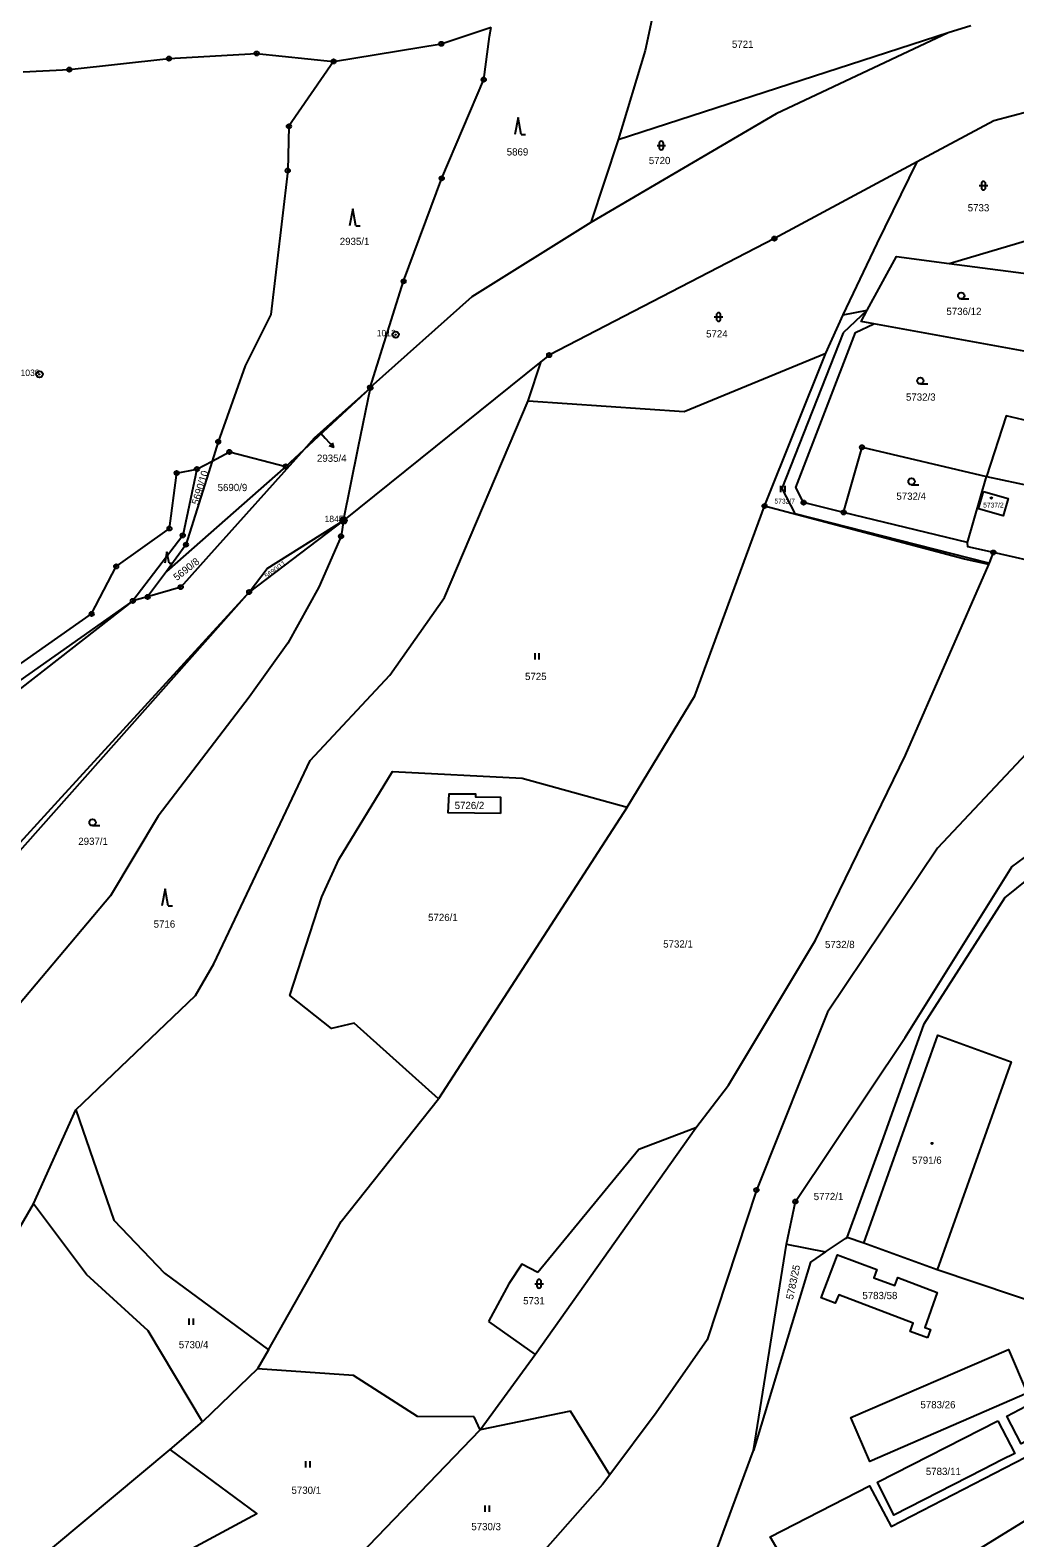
# Model space of a CAD drawing. Extents: x -644096 to -634268, y -1141430 to -1133463.
# Drawn here: x -640525.6 to -640294.6, y -1138714.8 to -1138361.1 of the extents above; entities that cross this region are included whole.
import ezdxf

# ---------------------------------------------------------------- set-up
doc = ezdxf.new("R2010")
doc.units = 0
for name, color, linetype in [('_CIVIL_CONSTRUCTION', 7, 'Continuous'), ('B_Hranice _3D', 7, 'Continuous'), ('M_Svah_Zarez', 7, 'Continuous'), ('svrsek_osa_sjezdy', 7, 'Continuous'), ('svrsek_osa_VRT', 7, 'Continuous'), ('svrsek_popisy_VRT', 7, 'Continuous'), ('terminal_VRT', 7, 'Continuous')]:
    doc.layers.add(name, color=color, linetype=linetype)

msp = doc.modelspace()

# ---------------------------------------------------------------- linework, layer by layer
at = {"layer": '_CIVIL_CONSTRUCTION'}
for centre, radius in [((-640429.15, -1138364.31), 0.5), ((-640429.15, -1138364.31), 0.0303), ((-640493.07, -1138367.77), 0.5), ((-640493.07, -1138367.77), 0.0303), ((-640472.51, -1138366.57), 0.5), ((-640472.51, -1138366.57), 0.0303), ((-640454.43, -1138368.44), 0.5), ((-640454.43, -1138368.44), 0.0303), ((-640516.46, -1138370.35), 0.5), ((-640516.46, -1138370.35), 0.0303), ((-640419.19, -1138372.7), 0.5), ((-640419.19, -1138372.7), 0.0303), ((-640464.92, -1138383.66), 0.5), ((-640464.92, -1138383.66), 0.0303), ((-640465.18, -1138394.05), 0.5), ((-640465.18, -1138394.05), 0.0303), ((-640429.05, -1138395.86), 0.5), ((-640429.05, -1138395.86), 0.0303), ((-640350.99, -1138410.01), 0.5), ((-640350.99, -1138410.01), 0.0303), ((-640437.99, -1138420.03), 0.5), ((-640437.99, -1138420.03), 0.0303), ((-640439.86, -1138432.54), 0.75), ((-640439.86, -1138432.54), 0.03), ((-640403.84, -1138437.33), 0.5), ((-640403.84, -1138437.33), 0.0303), ((-640523.44, -1138441.85), 0.75), ((-640523.44, -1138441.85), 0.03), ((-640445.87, -1138444.94), 0.5), ((-640445.77, -1138445.03), 0.5), ((-640445.87, -1138444.94), 0.0303), ((-640445.77, -1138445.03), 0.0303), ((-640481.51, -1138457.67), 0.5), ((-640481.51, -1138457.67), 0.0303), ((-640478.88, -1138460.05), 0.5), ((-640478.88, -1138460.05), 0.0303), ((-640330.42, -1138458.95), 0.5), ((-640330.42, -1138458.95), 0.0303), ((-640486.5, -1138464.09), 0.5), ((-640486.5, -1138464.09), 0.0303), ((-640465.66, -1138463.46), 0.5), ((-640465.66, -1138463.46), 0.0303), ((-640491.26, -1138465.01), 0.5), ((-640491.26, -1138465.01), 0.0303), ((-640344.14, -1138471.95), 0.5), ((-640353.3, -1138472.75), 0.5), ((-640353.3, -1138472.75), 0.0303), ((-640344.14, -1138471.95), 0.0303), ((-640334.73, -1138474.26), 0.5), ((-640334.73, -1138474.26), 0.0303), ((-640492.94, -1138478.03), 0.5), ((-640492.94, -1138478.03), 0.0303), ((-640452.1, -1138476.15), 0.75), ((-640452.09, -1138476.13), 0.5), ((-640452.1, -1138476.15), 0.03), ((-640452.09, -1138476.13), 0.0303), ((-640489.82, -1138479.65), 0.5), ((-640489.82, -1138479.65), 0.0303), ((-640489.07, -1138481.82), 0.5), ((-640489.07, -1138481.82), 0.0303), ((-640452.68, -1138479.84), 0.5), ((-640452.68, -1138479.84), 0.0303), ((-640299.59, -1138483.65), 0.5), ((-640299.59, -1138483.65), 0.0303), ((-640505.45, -1138486.91), 0.5), ((-640505.45, -1138486.91), 0.0303), ((-640490.29, -1138491.78), 0.5), ((-640490.29, -1138491.78), 0.0303), ((-640474.25, -1138492.94), 0.5), ((-640501.55, -1138495.02), 0.5), ((-640501.55, -1138495.02), 0.0303), ((-640498.07, -1138494.08), 0.5), ((-640498.07, -1138494.08), 0.0303), ((-640474.25, -1138492.94), 0.0303), ((-640511.21, -1138498.07), 0.5), ((-640511.21, -1138498.07), 0.0303), ((-640355.2, -1138633.25), 0.5), ((-640355.2, -1138633.25), 0.0303), ((-640346.06, -1138635.93), 0.5), ((-640346.06, -1138635.93), 0.0303)]:
    msp.add_circle(centre, radius, dxfattribs=at)
at = {"layer": 'B_Hranice _3D'}
msp.add_lwpolyline([(-640334.81, -1138432.1), (-640349.24, -1138468.6), (-640346.19, -1138474.52), (-640301.03, -1138486.03), (-640300.54, -1138486.15), (-640299.59, -1138483.65), (-640305.59, -1138482.32), (-640305.64, -1138481.34), (-640334.73, -1138474.26), (-640344.14, -1138471.95), (-640345.95, -1138468.44), (-640331.97, -1138432.02), (-640327.68, -1138430.03), (-640330.6, -1138429.48), (-640329.24, -1138426.79)], close=True, dxfattribs=at)
at = {"layer": 'M_Svah_Zarez'}
for centre in [(-640300.07, -1138470.88), (-640313.98, -1138622.3)]:
    msp.add_circle(centre, 0.175, dxfattribs=at)
at = {"layer": 'svrsek_osa_sjezdy'}
for p, q in [((-640411.13, -1138381.59), (-640411.88, -1138385.59)), ((-640410.38, -1138385.59), (-640411.13, -1138381.59)), ((-640410.38, -1138385.59), (-640409.38, -1138385.59)), ((-640378.53, -1138388.17), (-640376.53, -1138388.17)), ((-640378.03, -1138387.67), (-640378.03, -1138388.67)), ((-640377.03, -1138388.67), (-640377.03, -1138387.67)), ((-640302.42, -1138397.08), (-640302.42, -1138398.08)), ((-640301.42, -1138398.08), (-640301.42, -1138397.08)), ((-640302.92, -1138397.58), (-640300.92, -1138397.58)), ((-640449.94, -1138403.02), (-640450.69, -1138407.02)), ((-640449.19, -1138407.02), (-640449.94, -1138403.02)), ((-640449.19, -1138407.02), (-640448.19, -1138407.02)), ((-640307.14, -1138424.16), (-640305.39, -1138424.16)), ((-640365.1, -1138428.4), (-640363.1, -1138428.4)), ((-640364.6, -1138427.9), (-640364.6, -1138428.9)), ((-640363.6, -1138428.9), (-640363.6, -1138427.9)), ((-640316.73, -1138444.11), (-640314.98, -1138444.11)), ((-640318.8, -1138467.75), (-640317.05, -1138467.75)), ((-640349.44, -1138469.5), (-640349.44, -1138468)), ((-640348.44, -1138469.5), (-640348.44, -1138468)), ((-640493.53, -1138483.51), (-640494.03, -1138486.19)), ((-640493.03, -1138486.19), (-640493.53, -1138483.51)), ((-640493.03, -1138486.19), (-640492.36, -1138486.19)), ((-640407.16, -1138508.74), (-640407.16, -1138507.24)), ((-640406.16, -1138508.74), (-640406.16, -1138507.24)), ((-640511, -1138547.74), (-640509.25, -1138547.74)), ((-640493.99, -1138562.57), (-640494.74, -1138566.57)), ((-640493.24, -1138566.57), (-640493.99, -1138562.57)), ((-640493.24, -1138566.57), (-640492.24, -1138566.57)), ((-640407.2, -1138655.22), (-640405.2, -1138655.22)), ((-640406.7, -1138654.72), (-640406.7, -1138655.72)), ((-640405.7, -1138655.72), (-640405.7, -1138654.72)), ((-640488.33, -1138664.84), (-640488.33, -1138663.34)), ((-640487.33, -1138664.84), (-640487.33, -1138663.34)), ((-640460.91, -1138698.31), (-640460.91, -1138696.81)), ((-640459.91, -1138698.31), (-640459.91, -1138696.81)), ((-640418.85, -1138708.76), (-640418.85, -1138707.26)), ((-640417.85, -1138708.76), (-640417.85, -1138707.26))]:
    msp.add_line(p, q, dxfattribs=at)
for centre in [(-640307.14, -1138423.41), (-640316.73, -1138443.36), (-640318.8, -1138467), (-640511, -1138546.99)]:
    msp.add_circle(centre, 0.75, dxfattribs=at)
for centre, start, end in [((-640377.53, -1138387.67), 0, 180), ((-640377.53, -1138388.67), 180, 359.9879), ((-640301.92, -1138397.08), 0, 180), ((-640301.92, -1138398.08), 180, 359.9879), ((-640364.1, -1138427.9), 0, 180), ((-640364.1, -1138428.9), 180, 359.9879), ((-640406.2, -1138654.72), 0, 180), ((-640406.2, -1138655.72), 180, 359.9879)]:
    msp.add_arc(centre, 0.5, start, end, dxfattribs=at)
at = {"layer": 'svrsek_popisy_VRT'}
for p, q in [((-640457.43, -1138455.65), (-640456.4, -1138456.8)), ((-640456.4, -1138456.8), (-640454.39, -1138459.03)), ((-640454.39, -1138459.03), (-640455.43, -1138458.62)), ((-640454.39, -1138459.03), (-640454.69, -1138457.95))]:
    msp.add_line(p, q, dxfattribs=at)
at = {"layer": 'terminal_VRT'}
for p, q in [((-640310.19, -1138361.72), (-640387.64, -1138386.83)), ((-640304.87, -1138360.12), (-640310.19, -1138361.72)), ((-640387.64, -1138386.83), (-640394.07, -1138406.21)), ((-640309.96, -1138415.82), (-640275.63, -1138405.71)), ((-640309.96, -1138415.82), (-640285.96, -1138418.98)), ((-640338.94, -1138436.9), (-640334.86, -1138427.92)), ((-640334.86, -1138427.92), (-640329.24, -1138426.79)), ((-640291.51, -1138436.54), (-640327.68, -1138430.03)), ((-640405.75, -1138438.87), (-640452.09, -1138476.13)), ((-640408.75, -1138448.04), (-640405.75, -1138438.87)), ((-640372.15, -1138450.61), (-640338.94, -1138436.9)), ((-640353.3, -1138472.75), (-640338.94, -1138436.9)), ((-640461.37, -1138459.49), (-640445.77, -1138445.03)), ((-640445.77, -1138445.03), (-640445.87, -1138444.94)), ((-640408.75, -1138448.04), (-640372.15, -1138450.61)), ((-640465.66, -1138463.46), (-640461.37, -1138459.49)), ((-640465.66, -1138463.46), (-640493.68, -1138488.1)), ((-640486.5, -1138464.09), (-640482.93, -1138462.2)), ((-640305.64, -1138481.34), (-640301.2, -1138465.85)), ((-640301.2, -1138465.85), (-640265.27, -1138473.46)), ((-640306.36, -1138485.22), (-640353.3, -1138472.75)), ((-640305.64, -1138481.34), (-640334.73, -1138474.26)), ((-640452.09, -1138476.13), (-640474.25, -1138492.94)), ((-640300.67, -1138486.48), (-640306.36, -1138485.22)), ((-640300.67, -1138486.48), (-640299.59, -1138483.65)), ((-640271.94, -1138489.89), (-640299.59, -1138483.65)), ((-640493.68, -1138488.1), (-640498.07, -1138494.08)), ((-640498.07, -1138494.08), (-640501.55, -1138495.02)), ((-640385.51, -1138543.4), (-640429.8, -1138611.86)), ((-640524.82, -1138636.49), (-640514.94, -1138614.45)), ((-640407.16, -1138671.85), (-640369.39, -1138618.67)), ((-640338.99, -1138647.75), (-640334.3, -1138644.58)), ((-640334.3, -1138644.58), (-640333.88, -1138644.4)), ((-640330, -1138645.68), (-640333.88, -1138644.4)), ((-640355.87, -1138694.37), (-640348.13, -1138645.95)), ((-640348.13, -1138645.95), (-640338.99, -1138647.75)), ((-640312.78, -1138651.95), (-640330, -1138645.68)), ((-640418.06, -1138664.11), (-640407.16, -1138671.85)), ((-640469.7, -1138670.71), (-640472.29, -1138675.17)), ((-640420.06, -1138689.51), (-640407.16, -1138671.85)), ((-640472.29, -1138675.17), (-640485.16, -1138687.58)), ((-640420.06, -1138689.51), (-640421.43, -1138686.47)), ((-640398.84, -1138685.15), (-640420.06, -1138689.51)), ((-640389.64, -1138700.07), (-640398.84, -1138685.15)), ((-640378.72, -1138685.49), (-640389.64, -1138700.07)), ((-640492.77, -1138694.09), (-640485.16, -1138687.58)), ((-640465.31, -1138736.5), (-640420.06, -1138689.51)), ((-640374.92, -1138745.47), (-640355.87, -1138694.37)), ((-640389.64, -1138700.07), (-640391.31, -1138702.31)), ((-640391.31, -1138702.31), (-640420.08, -1138734.86))]:
    msp.add_line(p, q, dxfattribs=at)
for points in [[(-640378.17, -1138351.27), (-640381.33, -1138365.91), (-640387.64, -1138386.83)], [(-640454.43, -1138368.44), (-640429.15, -1138364.31), (-640417.45, -1138360.39)], [(-640445.87, -1138444.94), (-640437.99, -1138420.03), (-640429.05, -1138395.86), (-640419.19, -1138372.7), (-640417.84, -1138362.59), (-640417.45, -1138360.39)], [(-640310.19, -1138361.72), (-640350.6, -1138380.73), (-640394.07, -1138406.21)], [(-640527.24, -1138370.85), (-640516.46, -1138370.35), (-640493.07, -1138367.77), (-640472.51, -1138366.57), (-640454.43, -1138368.44)], [(-640454.43, -1138368.44), (-640464.92, -1138383.66), (-640465.18, -1138394.05), (-640469.16, -1138427.8), (-640475.15, -1138439.82), (-640481.51, -1138457.67), (-640482.93, -1138462.2)], [(-640262.19, -1138372.5), (-640299.51, -1138382.35), (-640317.51, -1138392.02)], [(-640317.51, -1138392.02), (-640350.99, -1138410.01), (-640403.84, -1138437.33), (-640405.75, -1138438.87)], [(-640334.86, -1138427.92), (-640326.84, -1138411.14), (-640317.51, -1138392.02)], [(-640394.07, -1138406.21), (-640422.02, -1138423.64), (-640445.87, -1138444.94)], [(-640329.24, -1138426.79), (-640322.31, -1138414.24), (-640309.96, -1138415.82)], [(-640327.68, -1138430.03), (-640330.6, -1138429.48), (-640329.24, -1138426.79)], [(-640334.73, -1138474.26), (-640344.14, -1138471.95), (-640345.95, -1138468.44), (-640331.97, -1138432.02), (-640327.68, -1138430.03)], [(-640461.37, -1138459.49), (-640458.94, -1138456.77), (-640445.77, -1138445.03)], [(-640452.09, -1138476.13), (-640448.69, -1138459.09), (-640445.77, -1138445.03)], [(-640514.94, -1138614.45), (-640486.84, -1138587.61), (-640482.52, -1138580.14), (-640459.96, -1138532.44), (-640441.2, -1138512.42), (-640428.39, -1138494.23), (-640408.75, -1138448.04)], [(-640291.31, -1138452.85), (-640296.6, -1138451.56), (-640301.2, -1138465.85)], [(-640461.37, -1138459.49), (-640483.75, -1138484.48), (-640490.29, -1138491.78), (-640498.07, -1138494.08)], [(-640482.93, -1138462.2), (-640478.88, -1138460.05), (-640465.66, -1138463.46)], [(-640334.73, -1138474.26), (-640330.42, -1138458.95), (-640301.2, -1138465.85)], [(-640588.56, -1138562.99), (-640572.5, -1138548.19), (-640570.45, -1138534.05), (-640562.96, -1138529.76), (-640552.16, -1138526.71), (-640511.21, -1138498.07), (-640505.45, -1138486.91), (-640492.94, -1138478.03), (-640491.32, -1138465.49), (-640491.26, -1138465.01), (-640486.5, -1138464.09)], [(-640486.5, -1138464.09), (-640489.82, -1138479.65), (-640501.55, -1138495.02)], [(-640482.93, -1138462.2), (-640489.07, -1138481.82), (-640493.68, -1138488.1)], [(-640301.92, -1138469.36), (-640296.14, -1138470.98), (-640297.29, -1138475.05), (-640303.1, -1138473.4), (-640301.92, -1138469.36)], [(-640385.51, -1138543.4), (-640369.65, -1138517.29), (-640353.3, -1138472.75)], [(-640452.09, -1138476.13), (-640452.68, -1138479.84), (-640457.92, -1138491.75), (-640465.14, -1138504.94), (-640474.28, -1138517.56), (-640495.6, -1138545.5), (-640506.79, -1138564.2), (-640539.24, -1138602.66)], [(-640474.25, -1138492.94), (-640470, -1138487.42), (-640452.09, -1138476.13)], [(-640299.59, -1138483.65), (-640305.59, -1138482.32), (-640305.64, -1138481.34)], [(-640369.39, -1138618.67), (-640361.77, -1138608.64), (-640341.34, -1138574.61), (-640320.2, -1138531.22), (-640300.67, -1138486.48)], [(-640501.55, -1138495.02), (-640550.4, -1138529.43), (-640561.89, -1138532.84), (-640566.34, -1138535.83), (-640569.2, -1138550.99)], [(-640501.55, -1138495.02), (-640542.28, -1138526.78), (-640559.8, -1138540.44)], [(-640474.25, -1138492.94), (-640519.13, -1138541.97), (-640538.6, -1138563.3)], [(-640474.25, -1138492.94), (-640537.36, -1138564.05), (-640538.6, -1138563.3)], [(-640283.24, -1138521.64), (-640312.74, -1138553.04), (-640338.5, -1138591.48), (-640355.2, -1138633.25), (-640366.74, -1138668.36), (-640378.72, -1138685.49)], [(-640429.8, -1138611.86), (-640449.57, -1138594.1), (-640454.94, -1138595.32), (-640464.71, -1138587.63), (-640457.22, -1138564.42), (-640453.18, -1138555.7), (-640440.61, -1138535.04), (-640410.15, -1138536.57), (-640385.51, -1138543.4)], [(-640415.28, -1138544.86), (-640421.33, -1138544.79), (-640427.55, -1138544.74), (-640427.32, -1138540.25), (-640421.15, -1138540.3), (-640421.15, -1138540.99), (-640415.27, -1138541.04), (-640415.28, -1138544.86)], [(-640348.13, -1138645.95), (-640346.06, -1138635.93), (-640320.29, -1138597.41), (-640295.27, -1138557.38), (-640290.83, -1138554.12)], [(-640333.88, -1138644.4), (-640325.4, -1138621.01), (-640315.83, -1138594.23), (-640296.91, -1138564.64), (-640288.05, -1138557.53)], [(-640330, -1138645.68), (-640312.62, -1138596.92), (-640295.43, -1138603.15), (-640312.78, -1138651.95)], [(-640469.7, -1138670.71), (-640452.68, -1138640.63), (-640429.8, -1138611.86)], [(-640514.94, -1138614.45), (-640505.98, -1138640.27), (-640494.09, -1138652.77), (-640469.7, -1138670.71)], [(-640369.39, -1138618.67), (-640382.77, -1138623.76), (-640406.47, -1138652.59)], [(-640564.91, -1138679.05), (-640555.46, -1138669.26), (-640534.55, -1138653.05), (-640524.82, -1138636.49)], [(-640485.16, -1138687.58), (-640497.94, -1138666.26), (-640512.41, -1138653.05), (-640524.82, -1138636.49)], [(-640338.99, -1138647.75), (-640342.53, -1138650.15), (-640355.87, -1138694.37)], [(-640406.47, -1138652.59), (-640410.27, -1138650.62), (-640413.33, -1138655.24), (-640418.06, -1138664.11)], [(-640315.06, -1138667.93), (-640319.12, -1138666.44), (-640318.41, -1138664.44), (-640335.88, -1138657.85), (-640336.71, -1138659.74), (-640340, -1138658.49), (-640336.15, -1138648.45), (-640326.92, -1138651.9), (-640327.65, -1138653.81), (-640322.74, -1138655.66), (-640322, -1138653.76), (-640312.8, -1138657.24), (-640315.72, -1138665.48), (-640314.38, -1138665.94), (-640315.06, -1138667.93)], [(-640271.62, -1138665.83), (-640285.53, -1138661.09), (-640312.78, -1138651.95)], [(-640291.67, -1138680.9), (-640328.56, -1138696.93), (-640333.06, -1138686.6), (-640296.07, -1138670.65), (-640291.67, -1138680.9)], [(-640421.43, -1138686.47), (-640434.72, -1138686.36), (-640449.78, -1138676.72), (-640472.29, -1138675.17)], [(-640288.68, -1138690.41), (-640293.06, -1138692.75), (-640296.4, -1138686.32), (-640291.94, -1138683.98), (-640288.68, -1138690.41)], [(-640298.53, -1138687.42), (-640294.56, -1138695.07), (-640297.59, -1138696.57), (-640302.02, -1138698.81), (-640322.99, -1138709.51), (-640326.81, -1138701.78), (-640298.53, -1138687.42)], [(-640541.31, -1138739.54), (-640526.49, -1138722.29), (-640492.77, -1138694.09)], [(-640465.31, -1138736.5), (-640490.72, -1138718.95), (-640472.46, -1138709.1), (-640492.77, -1138694.09)], [(-640346.91, -1138723.28), (-640351.96, -1138714.6), (-640328.67, -1138702.65), (-640323.62, -1138712.15), (-640287.24, -1138693.4), (-640281.02, -1138705.12), (-640291.03, -1138710.14), (-640337.48, -1138738.78)]]:
    msp.add_lwpolyline(points, dxfattribs=at)

# ---------------------------------------------------------------- texts
at = {"layer": '_CIVIL_CONSTRUCTION'}
for s, p in [('1012', (-640444.31, -1138432.92)), ('1039', (-640527.89, -1138442.23)), ('1845', (-640456.55, -1138476.53))]:
    msp.add_text(s, height=1.5, dxfattribs=at).set_placement(p)
at = {"layer": 'svrsek_osa_VRT'}
for s, height, p in [('5721', 1.7, (-640360.95, -1138365.25)), ('5869', 1.7, (-640413.8, -1138390.51)), ('5720', 1.7, (-640380.45, -1138392.53)), ('5733', 1.7, (-640305.61, -1138403.62)), ('2935/1', 1.7, (-640452.98, -1138411.51)), ('5736/12', 1.7, (-640310.61, -1138427.93)), ('5724', 1.7, (-640367.01, -1138433.2)), ('5732/3', 1.7, (-640320.11, -1138448.03)), ('2935/4', 1.7, (-640458.33, -1138462.38)), ('5690/9', 1.7, (-640481.64, -1138469.25)), ('5732/7', 1.14, (-640350.97, -1138472.17)), ('5732/4', 1.7, (-640322.36, -1138471.29)), ('5737/2', 1.14, (-640302, -1138473.1)), ('5725', 1.7, (-640409.5, -1138513.58)), ('5726/2', 1.7, (-640426.02, -1138543.85)), ('2937/1', 1.7, (-640514.34, -1138552.26)), ('5716', 1.7, (-640496.66, -1138571.67)), ('5726/1', 1.7, (-640432.25, -1138570.12)), ('5732/1', 1.7, (-640377.08, -1138576.35)), ('5732/8', 1.7, (-640339.11, -1138576.47)), ('5791/6', 1.7, (-640318.69, -1138627.08)), ('5772/1', 1.7, (-640341.76, -1138635.6)), ('5731', 1.7, (-640409.94, -1138660.06)), ('5783/58', 1.7, (-640330.34, -1138658.83)), ('5730/4', 1.7, (-640490.76, -1138670.36)), ('5783/26', 1.7, (-640316.71, -1138684.44)), ('5783/11', 1.7, (-640315.44, -1138700.1)), ('5730/1', 1.7, (-640464.31, -1138704.51)), ('5730/3', 1.7, (-640422.11, -1138713.05))]:
    msp.add_text(s, height=height, dxfattribs=at).set_placement(p)
for s, height, rotation, p in [('5690/10', 1.7, 73, (-640486.16, -1138472.6)), ('5690/8', 1.7, 38, (-640491.21, -1138490.37)), ('5690/11', 1.14, 37, (-640470.08, -1138489.79)), ('5783/25', 1.7, 78, (-640346.63, -1138659.03))]:
    msp.add_text(s, height=height, rotation=rotation, dxfattribs=at).set_placement(p)

doc.saveas('drawing.dxf')
